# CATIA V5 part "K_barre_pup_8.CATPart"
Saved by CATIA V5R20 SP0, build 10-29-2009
Part number: barre_pup_8
Bounding box of the stored display mesh (mm): x -77.401 to -65.436, y -211.465 to -93.351, z -161.295 to -71.979
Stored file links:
  G:\Khaled_CFAO_2011\ST2M\ST2M_GR2\gcausse\Khaled\CAD_ThinkMotion\K_barre_pup_8.CATPart
  C:\Documents and Settings\gcausse\Bureau\video thinkmotio\assemblage_gcausse\pupitre_think.CATProduct
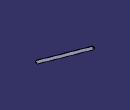
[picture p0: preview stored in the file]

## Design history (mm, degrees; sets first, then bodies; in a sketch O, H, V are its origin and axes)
Set1
  Sketch1 on Plane1, origin (-55.7229, 0, 6.855), H (0, 1, 0), V (0.1221, 0, 0.9925)
    line L1 (-97.3479, -80.048) -> (-210.4695, -164.9215)
    arc A1 centre (-208.9691, -166.9212) radius 2.5 from (-210.4695, -164.9215) to (-207.4688, -168.9209) ccw
    point P3 (-208.9691, -166.9212)
    line L2 (-207.4688, -168.9209) -> (-94.3472, -84.0475)
    arc A2 centre (-95.8475, -82.0477) radius 2.5 from (-94.3472, -84.0475) to (-97.3479, -80.048) ccw
    point P6 (-95.8475, -82.0477)
    reference projected point E1 (-208.9691, -166.9212) from Point1
    reference projected line E2 (-208.9691, -166.9212) -> (-95.8475, -82.0477) from Line1
    reference projected point E3 (-95.8475, -82.0477) from Point2
    distance L1 L2 = 5
    tangency: A1 L1, L2 A1, A2 L1, A2 L2
    coincidence: P3 E1, P6 E3
    parallelism: L2 E2
Set2
  Plane1: linked copy from another document
  Point1: linked copy from another document
  Line1: linked copy from another document
  Point2: linked copy from another document
Body1 (main body)
  Pad1: profile Sketch1, direction (0.9925, 0, -0.1221), length -1
  Sketch2 on start face of Pad1, origin (-73.4482, -178.1118, -137.2306), H (0.1221, 0, 0.9925), V (0, -1, 0)
    point P1 (63.124, -82.2642)
    reference projected point E1 (63.124, -82.2642) from Point2
    coincidence: P1 E1
  Hole1: placed by Sketch2, at (-65.7408, -95.8475, -74.5789) direction (-0.9925, 0, 0.1221), diameter 1, depth 1
  Sketch3 on start face of Pad1, origin (-73.8763, -181.3833, -140.7106), H (0.1221, 0, 0.9925), V (0, -1, 0)
    point P1 (-18.2432, 27.5859)
    reference projected point E1 (-18.2432, 27.5859) from Point1
    coincidence: P1 E1
  Hole2: placed by Sketch3, at (-76.1038, -208.9691, -158.8173) direction (-0.9925, 0, 0.1221), diameter 1, depth 1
